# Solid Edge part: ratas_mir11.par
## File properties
Author: Kalle
Template: Iso Part.par
Last saved by: Kalle
Revision: 2
Application: Solid Edge
Accuracy: 0,990
Username: Kalle
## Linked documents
ratas_mir1.par
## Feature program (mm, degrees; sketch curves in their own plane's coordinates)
part copy "CopiedPart_1"
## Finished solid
Body 1: solid body, 6 faces, 6 edges, 0 vertices.
  Faces by surface: cylinder 3, plane 3
  Edges by curve: circle 6
Bounding box of the edges (mm): 30.000 x 12.000 x 30.000, from (13.8781, -12, -41.601) to (43.8781, 0, -11.601).
Cylindrical faces by radius (mm): R4 x1, R10 x1, R15 x1
Planar faces by outward normal: +y 1, -y 2
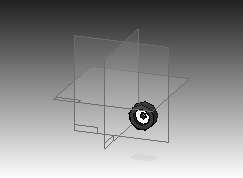
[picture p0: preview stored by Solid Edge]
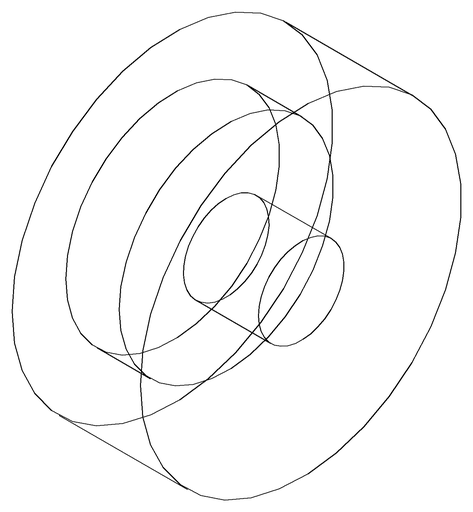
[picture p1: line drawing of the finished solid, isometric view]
